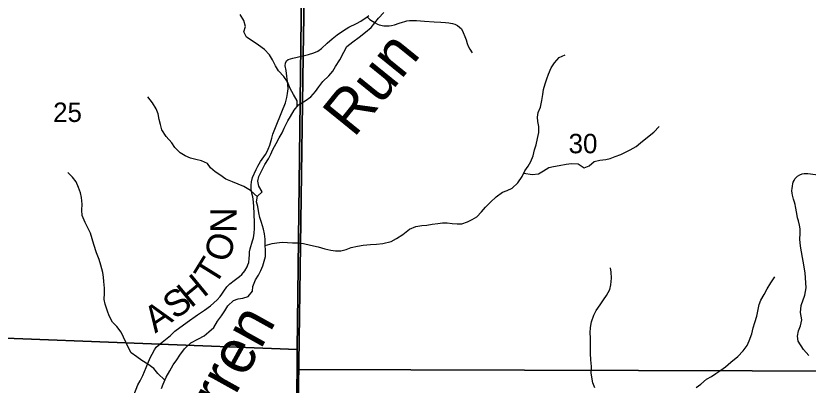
# Model space of a CAD drawing. Extents: x 0 to 34, y 0 to 22.
# Drawn here: x 3.957 to 5.667, y 19.604 to 20.4 of the extents above; entities that cross this region are included whole.
import ezdxf

# ---------------------------------------------------------------- set-up
doc = ezdxf.new("R2010")
doc.units = 0
for name, color, linetype in [('GM_X_County_Road', 7, 'Continuous'), ('GM_X_County_Road_Text', 7, 'Continuous'), ('GM_X_Minor_River', 7, 'Continuous'), ('GM_X_Minor_River_Text', 7, 'Continuous'), ('GM_X_Rail_Line', 7, 'Continuous'), ('GM_X_Section', 7, 'Continuous'), ('GM_X_Section_Text', 7, 'Continuous'), ('GM_X_Township_Road', 7, 'Continuous')]:
    doc.layers.add(name, color=color, linetype=linetype)

msp = doc.modelspace()

# ---------------------------------------------------------------- linework, layer by layer
at = {"layer": 'GM_X_County_Road'}
for points in [[(4.5704, 20.3127), (4.5775, 20.3143), (4.5888, 20.3169), (4.6006, 20.3205), (4.6092, 20.3243), (4.6169, 20.3303), (4.6293, 20.3418), (4.6397, 20.3509), (4.6505, 20.3592), (4.6644, 20.3689), (4.676, 20.3758), (4.6921, 20.3842), (4.7014, 20.3891), (4.7154, 20.3981), (4.7189, 20.4011)], [(4.2114, 19.5828), (4.2202, 19.6046), (4.2253, 19.6139), (4.2311, 19.625), (4.2385, 19.6421), (4.2471, 19.6633), (4.2514, 19.6714), (4.2566, 19.6806), (4.2601, 19.6858), (4.2725, 19.6969), (4.2906, 19.7114), (4.3001, 19.7206), (4.3269, 19.7401), (4.3494, 19.7559), (4.3642, 19.7657), (4.3769, 19.775), (4.3913, 19.7885), (4.398, 19.7957), (4.4019, 19.8006), (4.406, 19.8071), (4.4127, 19.8159), (4.419, 19.8229), (4.428, 19.8302), (4.4338, 19.8342), (4.4395, 19.8383), (4.4446, 19.8428), (4.4516, 19.851), (4.4561, 19.8591), (4.458, 19.8638), (4.4596, 19.8688), (4.461, 19.8772), (4.4613, 19.8854), (4.4615, 19.8914), (4.463, 19.8984), (4.4681, 19.9152), (4.4699, 19.9219), (4.4715, 19.9317), (4.4722, 19.9418), (4.4723, 19.9525), (4.4717, 19.975), (4.4711, 19.9888), (4.4699, 19.9992), (4.4687, 20.0101), (4.4667, 20.0184), (4.4649, 20.0271), (4.4647, 20.0353), (4.4654, 20.0426), (4.4682, 20.0517), (4.4756, 20.069), (4.4796, 20.0765), (4.4853, 20.0862), (4.4921, 20.0962), (4.4958, 20.1017), (4.4988, 20.1068), (4.502, 20.1129), (4.5051, 20.1215), (4.5093, 20.1368), (4.5119, 20.1453), (4.5174, 20.1597), (4.5315, 20.1936), (4.5394, 20.2128), (4.5423, 20.2246), (4.5434, 20.2334), (4.5446, 20.2433), (4.5445, 20.2522), (4.5406, 20.2828), (4.5382, 20.2925), (4.539, 20.2982), (4.541, 20.3038), (4.545, 20.3066), (4.5551, 20.3092), (4.5643, 20.3113), (4.5704, 20.3127)]]:
    msp.add_lwpolyline(points, dxfattribs=at)
at = {"layer": 'GM_X_Minor_River'}
for points in [[(4.5581, 20.197), (4.5675, 20.2085), (4.5815, 20.2169), (4.5939, 20.2261), (4.6037, 20.2372), (4.6109, 20.2475), (4.6199, 20.2589), (4.6324, 20.2715), (4.641, 20.2815), (4.6474, 20.2914), (4.6565, 20.3058), (4.6647, 20.3222), (4.6718, 20.3344), (4.6843, 20.3447), (4.6979, 20.3543), (4.7115, 20.365), (4.724, 20.3753), (4.7319, 20.3856), (4.7398, 20.3952), (4.7511, 20.4078)], [(4.5646, 20.205), (4.564, 20.2172), (4.5567, 20.2308), (4.5494, 20.2437), (4.5432, 20.258), (4.5356, 20.2694), (4.5241, 20.2822), (4.5172, 20.2924), (4.5114, 20.306), (4.5045, 20.3162), (4.4938, 20.3279), (4.4808, 20.3373), (4.4675, 20.3467), (4.4549, 20.3542), (4.4491, 20.3663), (4.4525, 20.3774), (4.449, 20.3906), (4.4409, 20.4031)], [(4.4955, 19.9055), (4.5106, 19.9095), (4.5205, 19.9114), (4.5318, 19.9123), (4.5432, 19.9116), (4.5543, 19.9109), (4.5656, 19.9114), (4.5782, 19.9095), (4.593, 19.9059), (4.6094, 19.9025), (4.6242, 19.8985), (4.6368, 19.8955), (4.6474, 19.8941), (4.6584, 19.8941), (4.6702, 19.8965), (4.6808, 19.9007), (4.6944, 19.9042), (4.7065, 19.9058), (4.7225, 19.9075), (4.7358, 19.9083), (4.7494, 19.9095), (4.7669, 19.9142), (4.7786, 19.9203), (4.7926, 19.9292), (4.8066, 19.9403), (4.8206, 19.946), (4.8331, 19.9488), (4.8445, 19.9492), (4.8558, 19.9516), (4.868, 19.9528), (4.8782, 19.954), (4.8881, 19.9541), (4.8991, 19.953), (4.9098, 19.9523), (4.92, 19.9524), (4.9318, 19.9566), (4.942, 19.9616), (4.9522, 19.967), (4.962, 19.9781), (4.971, 19.988), (4.9816, 19.9987), (4.994, 20.0106), (5.0073, 20.0205), (5.0175, 20.0236), (5.0285, 20.029), (5.0409, 20.0408), (5.05, 20.0538), (5.0559, 20.0664), (5.0627, 20.0763), (5.0687, 20.0866), (5.074, 20.0987), (5.0769, 20.1117), (5.0803, 20.1223), (5.0832, 20.136), (5.0858, 20.1489), (5.0857, 20.1622), (5.0837, 20.1728), (5.0829, 20.1823), (5.0847, 20.1918), (5.0896, 20.2039), (5.0925, 20.218), (5.0947, 20.2309), (5.0958, 20.2416), (5.0995, 20.2537), (5.1036, 20.2647), (5.1066, 20.2746), (5.1126, 20.2883), (5.1197, 20.299), (5.1299, 20.3108), (5.1428, 20.3166)], [(4.4785, 20.01), (4.4635, 20.0238), (4.4494, 20.0328), (4.4247, 20.0425), (4.4106, 20.0481), (4.3972, 20.0575), (4.3873, 20.0639), (4.3774, 20.0725), (4.3709, 20.0824), (4.3579, 20.088), (4.3454, 20.0909), (4.3343, 20.0939), (4.3222, 20.0987), (4.3119, 20.1051), (4.3, 20.1168), (4.2939, 20.127), (4.2816, 20.1402), (4.2721, 20.1546), (4.2689, 20.1659), (4.2662, 20.1773), (4.2639, 20.1894), (4.26, 20.2), (4.2523, 20.2133), (4.242, 20.2257)], [(4.2716, 19.5972), (4.2749, 19.6067), (4.2817, 19.6211), (4.2892, 19.6348), (4.2967, 19.6478), (4.3042, 19.6585), (4.311, 19.6691), (4.3211, 19.6829), (4.3351, 19.6955), (4.351, 19.7043), (4.3635, 19.7105), (4.3733, 19.7189), (4.3842, 19.7284), (4.3925, 19.7421), (4.4008, 19.7536), (4.4079, 19.7646), (4.4143, 19.7749), (4.4271, 19.7871), (4.4366, 19.7902), (4.4468, 19.7918), (4.4582, 19.7953), (4.4676, 19.8068), (4.4687, 19.8166), (4.4747, 19.8315), (4.4807, 19.8414), (4.4859, 19.8513), (4.4904, 19.8615), (4.493, 19.8714), (4.496, 19.8813), (4.4959, 19.8942), (4.4954, 19.9063), (4.495, 19.9192), (4.4938, 19.9306), (4.4914, 19.9405), (4.4871, 19.9549), (4.4837, 19.9658), (4.4817, 19.9761), (4.4793, 19.9893), (4.4766, 19.9992), (4.4788, 20.0117), (4.4886, 20.0213), (4.4813, 20.0334), (4.4793, 20.044), (4.4819, 20.0542), (4.4887, 20.0683), (4.4943, 20.0797), (4.5026, 20.0919), (4.5071, 20.1022), (4.5119, 20.1125), (4.5191, 20.1251), (4.5254, 20.1373), (4.5322, 20.1483), (4.5359, 20.1582), (4.5442, 20.1738), (4.5498, 20.1837), (4.5581, 20.197)], [(5.0534, 20.061), (5.0719, 20.0585), (5.0852, 20.0597), (5.0962, 20.0666), (5.1079, 20.0732), (5.1174, 20.0759), (5.1303, 20.0779), (5.1447, 20.0806), (5.1568, 20.0822), (5.1709, 20.0812), (5.1842, 20.0725), (5.1945, 20.0771), (5.2058, 20.0867), (5.2175, 20.089), (5.2308, 20.091), (5.2403, 20.093), (5.2505, 20.0972), (5.263, 20.1019), (5.2729, 20.1065), (5.2831, 20.1115), (5.2959, 20.1188), (5.3058, 20.1268), (5.3205, 20.1387), (5.3345, 20.1498), (5.3458, 20.1616)], [(4.2789, 19.6152), (4.2637, 19.6297), (4.2546, 19.6399), (4.2416, 19.6493), (4.229, 19.6576), (4.2183, 19.6651), (4.2061, 19.6738), (4.1988, 19.6874), (4.1942, 19.6972), (4.1896, 19.7078), (4.1846, 19.7184), (4.175, 19.7308), (4.1654, 19.7403), (4.1585, 19.7535), (4.1547, 19.7641), (4.1496, 19.7792), (4.1473, 19.7891), (4.1483, 19.8024), (4.1486, 19.8134), (4.1466, 19.8274), (4.1462, 19.8373), (4.145, 19.8468), (4.1403, 19.863), (4.1365, 19.8755), (4.1314, 19.8892), (4.1256, 19.9073), (4.1179, 19.9319), (4.1117, 19.9452), (4.1063, 19.955), (4.1001, 19.9702), (4.0997, 19.9812), (4.1, 19.9941), (4.0987, 20.0089), (4.0964, 20.0191), (4.0921, 20.0301), (4.0875, 20.0426), (4.0795, 20.0524), (4.0695, 20.0629)], [(5.2067, 19.5988), (5.2029, 19.6094), (5.2005, 19.6211), (5.1993, 19.631), (5.1996, 19.6446), (5.1984, 19.659), (5.1979, 19.6727), (5.1974, 19.6848), (5.1973, 19.7061), (5.1968, 19.7171), (5.1979, 19.7288), (5.1997, 19.741), (5.2049, 19.7554), (5.2098, 19.7653), (5.2188, 19.7775), (5.226, 19.7882), (5.232, 19.7977), (5.2391, 19.8107), (5.2413, 19.8206), (5.2428, 19.8346), (5.2423, 19.8479), (5.2407, 19.8574)], [(5.5588, 19.7635), (5.5617, 19.7783), (5.5651, 19.7878), (5.5726, 19.7996), (5.5793, 19.8118), (5.5868, 19.8251), (5.5955, 19.8381)], [(5.4258, 19.5991), (5.4356, 19.6067), (5.4481, 19.6174), (5.4587, 19.6228), (5.4685, 19.6293), (5.4787, 19.6362), (5.4889, 19.6439), (5.5006, 19.6538), (5.5157, 19.6661), (5.527, 19.6783), (5.5357, 19.6897), (5.5402, 19.6996), (5.5462, 19.7148), (5.5487, 19.7277), (5.5521, 19.7395), (5.5566, 19.7528), (5.5588, 19.7635)]]:
    msp.add_lwpolyline(points, dxfattribs=at)
at = {"layer": 'GM_X_Rail_Line'}
msp.add_lwpolyline([(4.5874, 20.9), (2.1, 20.9), (2.1, 18.7171), (2.7864, 18.6994), (2.7892, 18.6993), (2.9222, 18.6946), (2.9234, 18.6945), (3.8442, 18.6615), (3.8456, 18.6615), (4.5462, 18.6416), (4.5515, 18.7621), (4.5519, 18.771), (4.5566, 18.8683), (4.5569, 18.8737), (4.5569, 18.8748), (4.5571, 18.8875), (4.5772, 20.3136), (4.5773, 20.3149)], close=True, dxfattribs=at)
msp.add_lwpolyline([(8.8193, 20.9), (4.5874, 20.9), (4.5773, 20.3149), (4.5772, 20.3136), (4.5571, 18.8875), (4.5569, 18.8748), (4.5569, 18.8737), (4.5566, 18.8683), (4.5519, 18.771), (4.5515, 18.7621), (4.5462, 18.6416), (4.7887, 18.6396), (4.7954, 18.6396), (4.8076, 18.6387), (4.8445, 18.636), (4.8458, 18.6359), (5.4171, 18.6266), (7.3845, 18.6186)], dxfattribs=at)
at = {"layer": 'GM_X_Section'}
for points in [[(4.5766, 20.6934), (4.5761, 20.6339), (4.5646, 19.6808), (3.5637, 19.7201), (3.5738, 20.7275)], [(4.5761, 20.6339), (5.7984, 20.651), (5.7918, 19.6342), (4.5644, 19.6379), (4.5646, 19.6808)], [(4.5646, 19.6808), (4.5644, 19.6379), (4.5473, 18.6426), (3.5541, 18.6711), (3.5637, 19.7201)], [(5.7918, 19.6342), (5.7885, 18.6247), (5.7131, 18.626), (4.5473, 18.6426), (4.5644, 19.6379)]]:
    msp.add_lwpolyline(points, close=True, dxfattribs=at)
at = {"layer": 'GM_X_Township_Road'}
for points in [[(4.7154, 20.3981), (4.7209, 20.3929), (4.7269, 20.3889), (4.7328, 20.3852), (4.7378, 20.3824), (4.7414, 20.381), (4.7446, 20.3802), (4.7477, 20.3797), (4.7511, 20.3793), (4.7548, 20.379), (4.7589, 20.3791), (4.7631, 20.3793), (4.7681, 20.3798), (4.7747, 20.3813), (4.7845, 20.3847), (4.7914, 20.387), (4.7964, 20.3883), (4.8012, 20.3894), (4.8068, 20.3901), (4.8126, 20.3903), (4.8168, 20.3905), (4.8222, 20.3902), (4.8394, 20.3891), (4.8604, 20.3878), (4.8743, 20.387), (4.8846, 20.3861), (4.8915, 20.3853), (4.8952, 20.3847), (4.8996, 20.3837), (4.905, 20.3822), (4.9102, 20.3796), (4.9151, 20.3764), (4.9188, 20.3722), (4.9227, 20.3647), (4.9264, 20.356), (4.9289, 20.3485), (4.9311, 20.3406), (4.9337, 20.3352), (4.9369, 20.3285), (4.9422, 20.3211)], [(5.6686, 19.6681), (5.6572, 19.681), (5.6457, 19.6988), (5.6446, 19.7098), (5.6468, 19.7216), (5.6509, 19.7322), (5.6535, 19.7448), (5.6512, 19.7607), (5.6523, 19.7763), (5.6606, 19.7979), (5.6635, 19.8143), (5.6614, 19.8466), (5.657, 19.8716), (5.6515, 19.8997), (5.6499, 19.9107), (5.6495, 19.9197), (5.6501, 19.9307), (5.6504, 19.9416), (5.6491, 19.9493), (5.6465, 19.9584), (5.6448, 19.9651), (5.6432, 19.9742), (5.6399, 19.9896), (5.6393, 19.9938), (5.6382, 19.9987), (5.6361, 20.0052), (5.6337, 20.0139), (5.6329, 20.0183), (5.6326, 20.023), (5.6329, 20.0286), (5.6335, 20.0329), (5.6347, 20.0394), (5.6354, 20.0421), (5.637, 20.0457), (5.639, 20.0489), (5.6413, 20.0518), (5.6446, 20.0546), (5.6493, 20.0575), (5.6545, 20.0595), (5.6587, 20.0603), (5.6628, 20.0605), (5.667, 20.0603), (5.6942, 20.0567)]]:
    msp.add_lwpolyline(points, dxfattribs=at)

# ---------------------------------------------------------------- texts
at = {"layer": 'GM_X_County_Road_Text'}
for s, rotation, p in [('N', 89.6471, (4.4334, 19.9323)), ('O', 72.5189, (4.4156, 19.8663)), ('T', 58.2253, (4.3867, 19.8162)), ('H', 39.5112, (4.3349, 19.7692)), ('S', 35.8173, (4.3006, 19.7443)), ('A', 34.1952, (4.2579, 19.7152))]:
    msp.add_text(s, height=0.0568, rotation=rotation, dxfattribs=at).set_placement(p)
at = {"layer": 'GM_X_Minor_River_Text'}
for s, height, rotation, p in [('Run', 0.09472, 51.0195, (4.6867, 20.1359)), ('Warren', 0.09471, 61.0128, (4.3184, 19.3783))]:
    msp.add_text(s, height=height, rotation=rotation, dxfattribs=at).set_placement(p)
at = {"layer": 'GM_X_Section_Text'}
for s, p in [('25', (4.0374, 20.1717)), ('30', (5.1503, 20.1042))]:
    msp.add_text(s, height=0.04186, rotation=0, dxfattribs=at).set_placement(p)

doc.saveas('drawing.dxf')
